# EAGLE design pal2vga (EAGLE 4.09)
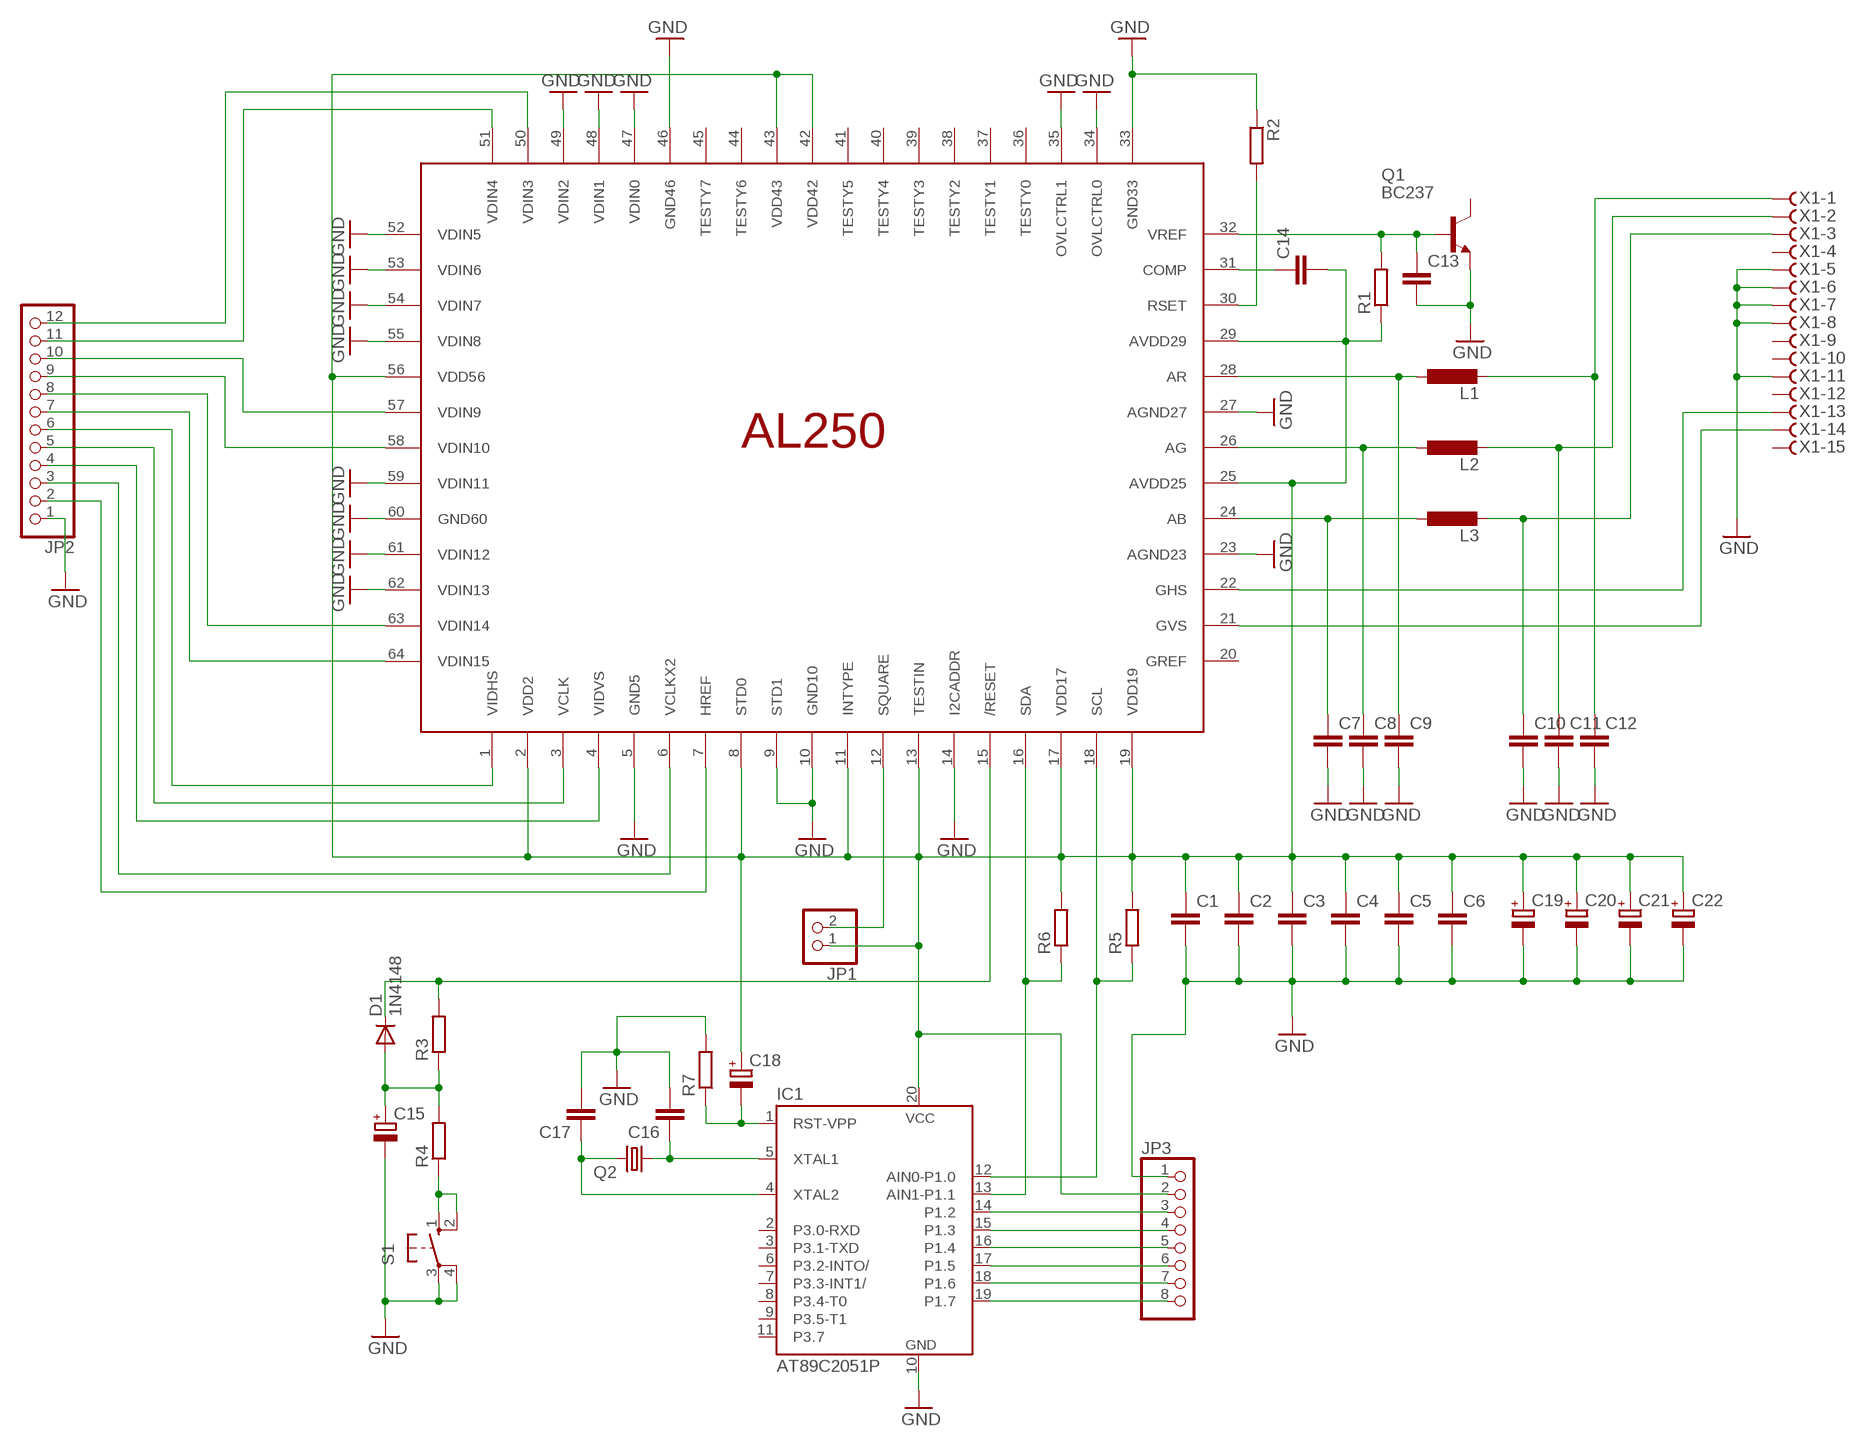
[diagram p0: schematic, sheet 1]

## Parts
C1  C-EUC1206  [C1206]
C2  C-EUC1206  [C1206]
C3  C-EUC1206  [C1206]
C4  C-EUC1206  [C1206]
C5  C-EUC1206  [C1206]
C6  C-EUC1206  [C1206]
C7  C-EUC1206  [C1206]
C8  C-EUC1206  [C1206]
C9  C-EUC1206  [C1206]
C10  C-EUC1206  [C1206]
C11  C-EUC1206  [C1206]
C12  C-EUC1206  [C1206]
C13  C-EUC1206  [C1206]
C14  C-EUC1206  [C1206]
C15  CPOL-EUE2,5-6E  [E2,5-6E]
C16  C-EU050-024X044  [C050-024X044]
C17  C-EU050-024X044  [C050-024X044]
C18  CPOL-EUE3.5-8  [E3,5-8]
C19  CPOL-EUCT6032  [CT6032]
C20  CPOL-EUCT6032  [CT6032]
C21  CPOL-EUCT6032  [CT6032]
C22  CPOL-EUCT6032  [CT6032]
D1  1N4148  [DO35-10]
IC1  AT89C2051P  [DIL20]
JP1  PINHD-1X2  [1X02]
JP2  PINHD-1X12  [1X12]
JP3  PINHD-1X8  [1X08]
L1  L-EUL1812  [L1812]
L2  L-EUL1812  [L1812]
L3  L-EUL1812  [L1812]
Q1  BC237  [TO92]
Q2  CRYTALHC49U-V  [HC49U-V]
R1  R-EU_M1206  [M1206]
R2  R-EU_M1206  [M1206]
R3  R-EU_M1206  [M1206]
R4  R-EU_M1206  [M1206]
R5  R-EU_0207/10  [0207/10]
R6  R-EU_0207/10  [0207/10]
R7  R-EU_0207/10  [0207/10]
S1  10-XX  [B3F-10XX]
U$1  AL250  [QFP64]
X1  F15HDHS  [HDF15H]

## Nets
GND: C1.2 C2.2 C3.2 C4.2 C5.2 C6.2 C7.2 C8.2 C9.2 C10.2 C11.2 C12.2 C13.2 C15.- C16.2 C17.2 C19.- C20.- C21.- C22.- IC1.10(GND) JP2.1 JP3.1 Q1.1(E) R2.1 R7.2 S1.3(P) S1.4(P1) U$1.5(GND5) U$1.9(STD1) U$1.10(GND10) U$1.14(I2CADDR) U$1.23(AGND23) U$1.27(AGND27) U$1.33(GND33) U$1.34(OVLCTRL0) U$1.35(OVLCTRL1) U$1.46(GND46) U$1.47(VDIN0) U$1.48(VDIN1) U$1.49(VDIN2) U$1.52(VDIN5) U$1.53(VDIN6) U$1.54(VDIN7) U$1.55(VDIN8) U$1.59(VDIN11) U$1.60(GND60) U$1.61(VDIN12) U$1.62(VDIN13) X1.5 X1.6 X1.7 X1.8 X1.11
N$1: C13.1 Q1.2(B) R1.2 U$1.32(VREF)
N$2: C14.1 U$1.31(COMP)
N$3: JP1.2 U$1.12(SQUARE)
N$5: JP2.11 U$1.51(VDIN4)
N$7: R2.2 U$1.30(RSET)
N$8: JP2.12 U$1.50(VDIN3)
N$9: U$1.22(GHS) X1.13
N$10: U$1.21(GVS) X1.14
N$11: JP2.10 U$1.57(VDIN9)
N$12: JP2.9 U$1.58(VDIN10)
N$13: JP2.8 U$1.63(VDIN14)
N$14: JP2.7 U$1.64(VDIN15)
N$15: JP2.6 U$1.1(VIDHS)
N$16: IC1.12(AIN0-P1.0) R5.1 U$1.18(SCL)
N$17: IC1.13(AIN1-P1.1) R6.1 U$1.16(SDA)
N$18: JP2.5 U$1.3(VCLK)
N$19: C7.1 L3.1 U$1.24(AB)
N$20: C8.1 L2.1 U$1.26(AG)
N$21: C9.1 L1.1 U$1.28(AR)
N$22: JP2.4 U$1.4(VIDVS)
N$23: JP2.3 U$1.6(VCLKX2)
N$24: JP2.2 U$1.7(HREF)
N$25: C16.1 IC1.5(XTAL1) Q2.1
N$26: C17.1 IC1.4(XTAL2) Q2.2
N$27: C12.1 L1.2 X1.1
N$28: C15.+ D1.A R3.1 R4.2
N$29: C11.1 L2.2 X1.2
N$30: C10.1 L3.2 X1.3
N$32: R4.1 S1.1(S) S1.2(S1)
N$34: C18.- IC1.1(RST-VPP) R7.1
N$35: C1.1 C2.1 C3.1 C4.1 C5.1 C6.1 C14.2 C18.+ C19.+ C20.+ C21.+ C22.+ IC1.20(VCC) JP1.1 JP3.2 R1.1 R5.2 R6.2 U$1.2(VDD2) U$1.8(STD0) U$1.11(INTYPE) U$1.13(TESTIN) U$1.17(VDD17) U$1.19(VDD19) U$1.25(AVDD25) U$1.29(AVDD29) U$1.42(VDD42) U$1.43(VDD43) U$1.56(VDD56)
N$36: D1.C R3.2 U$1.15(/RESET)
N$39: IC1.19(P1.7) JP3.8
N$40: IC1.18(P1.6) JP3.7
N$41: IC1.17(P1.5) JP3.6
N$42: IC1.16(P1.4) JP3.5
N$43: IC1.15(P1.3) JP3.4
N$44: IC1.14(P1.2) JP3.3
Unconnected: IC1.2(P3.0-RXD) IC1.3(P3.1-TXD) IC1.6(P3.2-INTO/) IC1.7(P3.3-INT1/) IC1.8(P3.4-T0) IC1.9(P3.5-T1) IC1.11(P3.7) Q1.3(C) U$1.20(GREF) U$1.36(TESTY0) U$1.37(TESTY1) U$1.38(TESTY2) U$1.39(TESTY3) U$1.40(TESTY4) U$1.41(TESTY5) U$1.44(TESTY6) U$1.45(TESTY7) X1.4 X1.9 X1.10 X1.12 X1.15

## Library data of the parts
C1-C14 C16 C17 = rcl:C-EU: CAPACITOR, European symbol
C15 C18-C22 = rcl:CPOL-EU: POLARIZED CAPACITOR, European symbol
D1 = diode:1N4148: DIODE
IC1 = atmel:AT89C2051: 80C31 MICROCONTROLLER 2 Kbytes FLASH 2.7 V
JP1 = pinhead:PINHD-1X2: PIN HEADER
JP2 = pinhead:PINHD-1X12: PIN HEADER
JP3 = pinhead:PINHD-1X8: PIN HEADER
L1-L3 = rcl:L-EU: INDUCTOR, European symbol
Q1 = transistor-npn:BC237: NPN Transistor
Q2 = crystal:CRYTAL: CRYSTAL
R1-R7 = rcl:R-EU_: RESISTOR, European symbol
S1 = switch-omron:10-XX: OMRON SWITCH
U$1 = averlog:AL250: Averlogic AL250 scandoubler
X1 = con-subd:F15?S: SUB-D

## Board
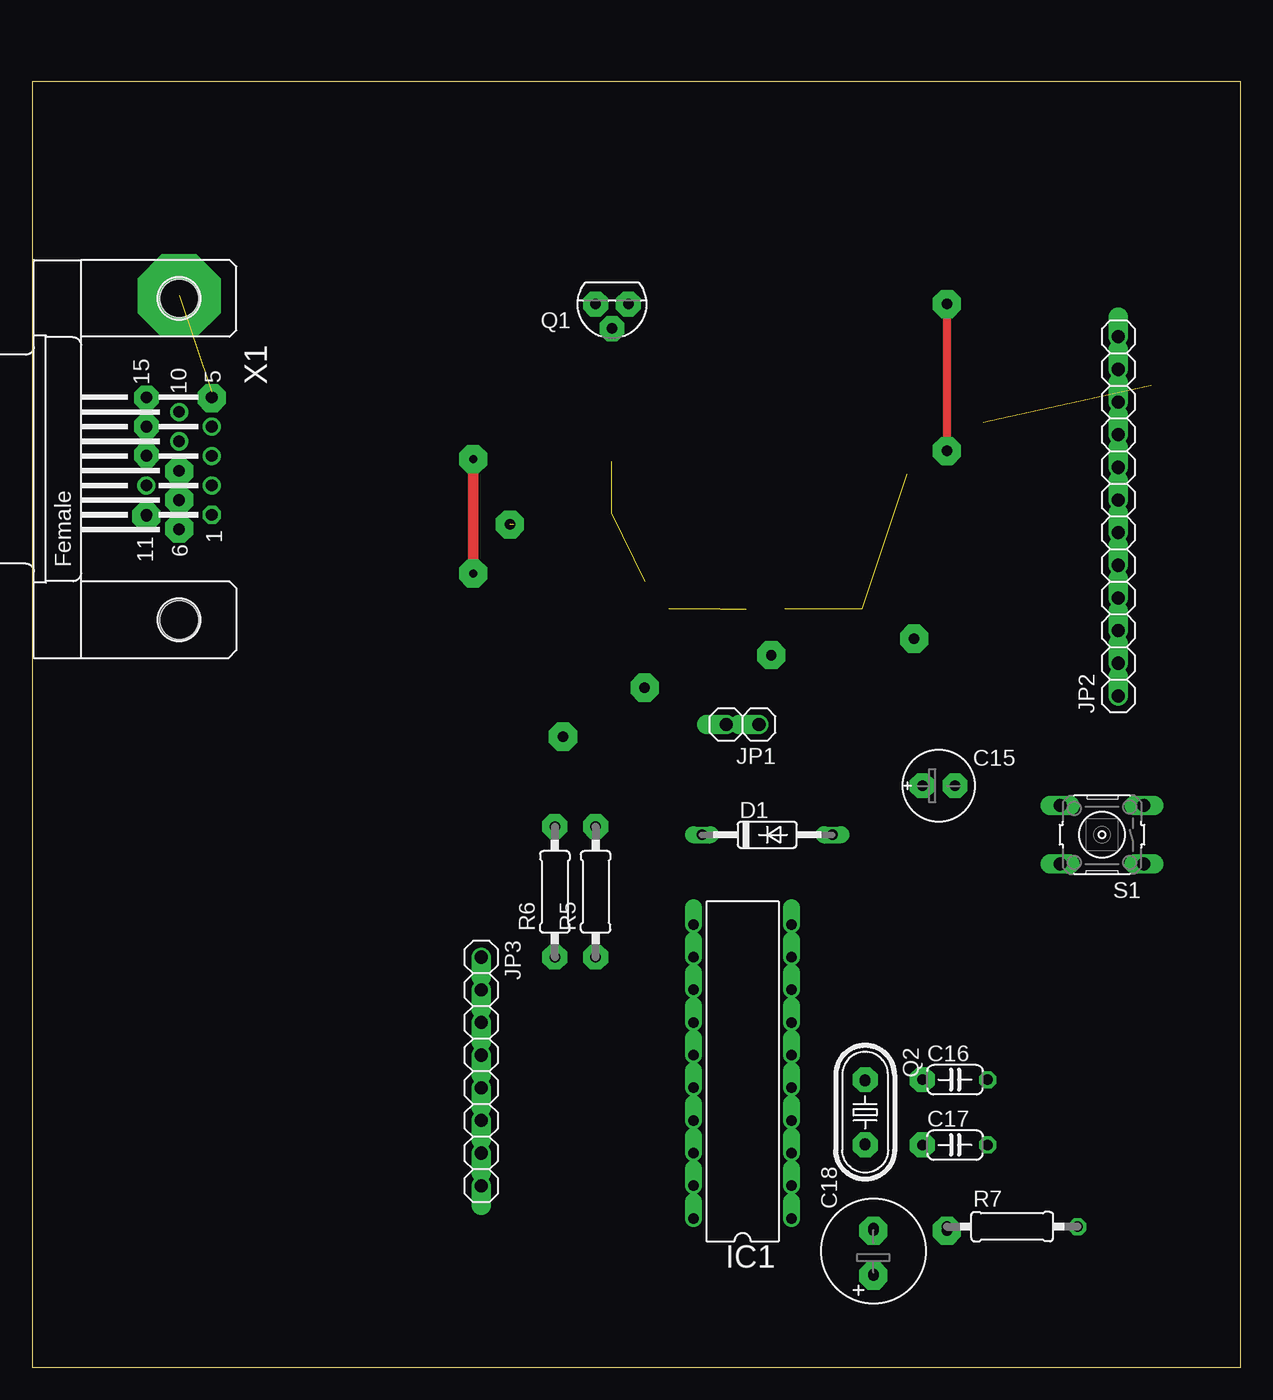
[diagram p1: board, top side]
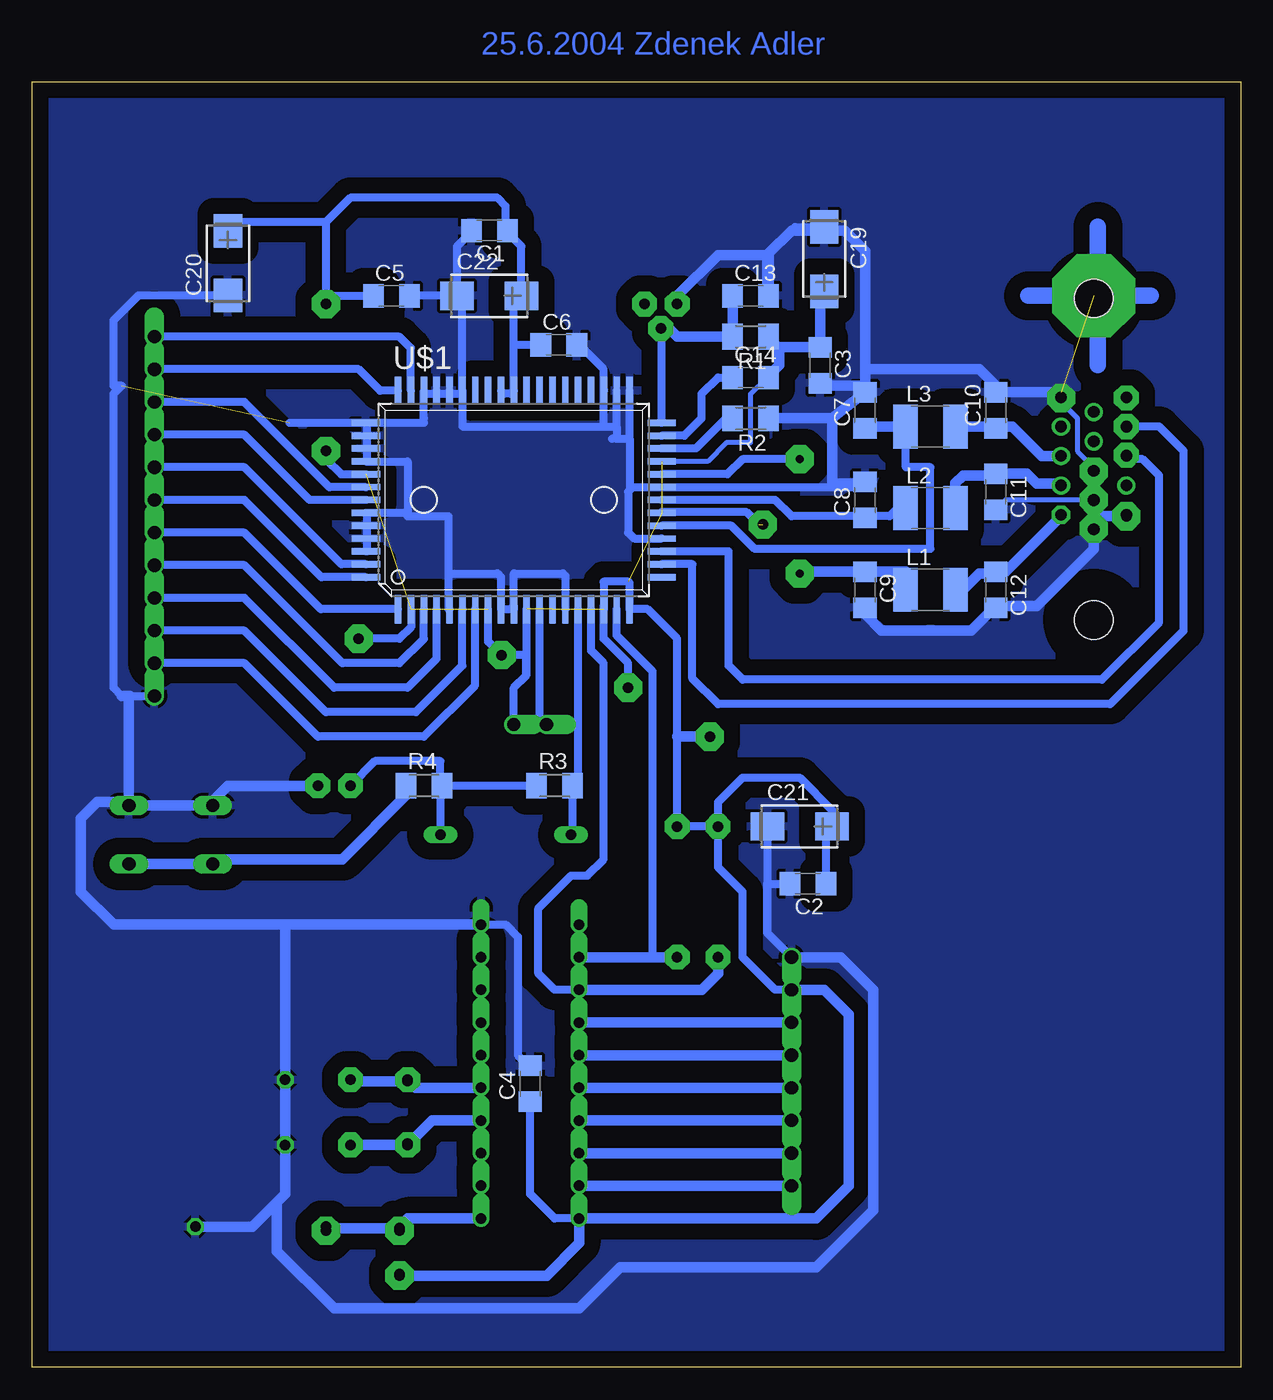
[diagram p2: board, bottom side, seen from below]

Size 93.96 x 100 mm. Coordinates in mm from the lower left corner, seen from the top.
Outline: 0,0 93.96,0 93.96,100 0,100 0,0
Copper layers used: Top, Bottom

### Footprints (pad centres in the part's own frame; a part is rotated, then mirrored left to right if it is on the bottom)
C1206 = smd 1.6 x 1.8: 1 -1.4,0; 2 1.4,0
E2,5-6E = drill 0.813 pad 1.575 round: + -1.27,0 | drill 0.813 pad 1.575 octagon: - 1.27,0
C050-024X044 = drill 0.813 octagon: 1 -2.54,0; 2 2.54,0
E3,5-8 = drill 0.813 pad 1.6 round: + -1.778,0 | drill 0.813 pad 1.6 octagon: - 1.778,0
CT6032 = smd 2.6 x 2.2: + 2.5,0; - -2.5,0
DO35-10 = drill 0.813 long: A 5.08,0; C -5.08,0
DIL20 = drill 0.813 offset: 1 -11.43,-3.81; 2 -8.89,-3.81; 3 -6.35,-3.81; 4 -3.81,-3.81; 5 -1.27,-3.81; 6 1.27,-3.81; 7 3.81,-3.81; 8 6.35,-3.81; 9 8.89,-3.81; 10 11.43,-3.81; 11 11.43,3.81; 12 8.89,3.81; 13 6.35,3.81; 14 3.81,3.81; 15 1.27,3.81; 16 -1.27,3.81; 17 -3.81,3.81; 18 -6.35,3.81; 19 -8.89,3.81; 20 -11.43,3.81
1X02 = drill 1.016 offset: 1 -1.27,0; 2 1.27,0
1X12 = drill 1.016 offset: 1 -13.97,0; 2 -11.43,0; 3 -8.89,0; 4 -6.35,0; 5 -3.81,0; 6 -1.27,0; 7 1.27,0; 8 3.81,0; 9 6.35,0; 10 8.89,0; 11 11.43,0; 12 13.97,0
1X08 = drill 1.016 offset: 1 -8.89,0; 2 -6.35,0; 3 -3.81,0; 4 -1.27,0; 5 1.27,0; 6 3.81,0; 7 6.35,0; 8 8.89,0
L1812 = smd 1.9 x 3.4: 1 -1.95,0; 2 1.95,0
TO92 = drill 0.813 octagon: 1 1.27,0; 2 0,1.905; 3 -1.27,0
HC49U-V = drill 0.813 round: 1 -2.413,0; 2 2.413,0
M1206 = smd 1.6 x 2: 1 -1.4,0; 2 1.4,0
0207/10 = drill 0.813 octagon: 1 -5.08,0; 2 5.08,0
B3F-10XX = drill 1.016 long: 1 -3.251,2.261; 2 3.251,2.261; 3 -3.251,-2.261; 4 3.251,-2.261
QFP64 = smd 0.5 x 2.2: 1 -9,-8.5; 2 -8,-8.5; 3 -7,-8.5; 4 -6,-8.5; 5 -5,-8.5; 6 -4,-8.5; 7 -3,-8.5; 8 -2,-8.5; 9 -1,-8.5; 10 0,-8.5; 11 1,-8.5; 12 2,-8.5; 13 3,-8.5; 14 4,-8.5; 15 5,-8.5; 16 6,-8.5; 17 7,-8.5; 18 8,-8.5; 19 9,-8.5; 33 9,8.5; 34 8,8.5; 35 7,8.5; 36 6,8.5; 37 5,8.5; 38 4,8.5; 39 3,8.5; 40 2,8.5; 41 1,8.5; 42 0,8.5; 43 -1,8.5; 44 -2,8.5; 45 -3,8.5; 46 -4,8.5; 47 -5,8.5; 48 -6,8.5; 49 -7,8.5; 50 -8,8.5; 51 -9,8.5 | smd 2.2 x 0.5: 20 11.5,-6; 21 11.5,-5; 22 11.5,-4; 23 11.5,-3; 24 11.5,-2; 25 11.5,-1; 26 11.5,0; 27 11.5,1; 28 11.5,2; 29 11.5,3; 30 11.5,4; 31 11.5,5; 32 11.5,6; 52 -11.5,6; 53 -11.5,5; 54 -11.5,4; 55 -11.5,3; 56 -11.5,2; 57 -11.5,1; 58 -11.5,0; 59 -11.5,-1; 60 -11.5,-2; 61 -11.5,-3; 62 -11.5,-4; 63 -11.5,-5; 64 -11.5,-6
HDF15H = drill 0.9 octagon: 1 4.329,2.54 | drill 0.9 round: 2 2.043,2.54; 3 -0.243,2.54; 4 -2.529,2.54; 5 -4.815,2.54; 6 5.472,0; 7 3.186,0; 8 0.9,0; 9 -1.386,0; 10 -3.672,0; 11 4.329,-2.54; 12 2.043,-2.54; 13 -0.243,-2.54; 14 -2.529,-2.54; 15 -4.815,-2.54 | hole 3: -12.5,0; 12.5,0

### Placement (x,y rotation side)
C1  58.41,88.42 180 bottom
C2  33.65,37.62 180 bottom
C3  32.7,77.94 270 bottom
C4  55.24,22.06 90 bottom
C5  66.03,83.34 0 bottom
C6  53.02,79.53 0 bottom
C7  29.2,74.45 90 bottom
C8  29.2,67.46 90 bottom
C9  29.2,60.48 270 bottom
C10  19.04,74.45 90 bottom
C11  19.04,68.1 270 bottom
C12  19.04,60.48 270 bottom
C13  38.1,83.34 0 bottom
C14  38.1,76.99 0 bottom
C15  70.48,45.24 0 top
C16  71.75,22.38 0 top
C17  71.75,17.3 0 top
C18  65.4,9.04 90 top
C19  32.38,86.19 270 bottom
C20  78.73,85.88 90 bottom
C21  34.29,42.06 0 bottom
C22  58.41,83.34 0 bottom
D1  57.15,41.43 0 top
IC1  55.24,23.01 90 top
JP1  55.24,50 180 top
JP2  84.45,66.19 90 top
JP3  34.92,23.01 270 top
L1  24.12,60.48 0 bottom
L2  24.12,66.83 0 bottom
L3  24.12,73.18 0 bottom
Q1  45.08,82.7 180 top
Q2  64.77,19.84 270 top
R1  38.1,80.16 180 bottom
R2  38.1,73.81 180 bottom
R3  53.34,45.24 0 bottom
R4  63.5,45.24 0 bottom
R5  43.81,36.98 90 top
R6  40.64,36.98 90 top
R7  76.19,10.95 0 top
S1  83.18,41.43 180 top
U$1  56.51,67.46 0 bottom
X1  11.43,70.64 270 top

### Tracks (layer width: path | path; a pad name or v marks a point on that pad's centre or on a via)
GND  (via drill 0.81 pad 2.18, 0.81 pad 6.45)  (2 unrouted)
  Bottom 0.406: C11.2 18.28,67.46 v11.43,67.46 | X1.5 v13.97,75.4 13.97,75.08 12.7,73.81 12.7,71.27 11.43,70 X1.8
  Bottom 0.61: 29.2,68.73 29.47,68.46 U$1.27 47.26,68.46 47.62,68.1 | U$1.23 47.16,64.46 47.62,64.92 47.62,68.1 | 47.51,72.22 47.51,68.21 47.62,68.1 | 47.51,72.22 U$1.33 | 48.51,73.18 48.51,72.22 | 48.51,72.22 48.89,72.22 | 48.51,72.22 47.51,72.22 | 49.51,73.18 49.53,75.72 | 48.51,73.18 U$1.34 | 49.51,73.18 48.51,73.18 | 49.51,73.18 U$1.35 49.51,76.02 49.53,76.03 49.53,77.62 51.43,79.53 C6.2 | 61.51,75.72 61.59,75.72 | U$1.46 60.51,75.72 61.51,75.72 | U$1.46 60.51,73.18 49.51,73.18 | 61.51,75.72 U$1.47 | 62.51,75.72 61.51,75.72 | 62.51,75.72 U$1.48 | 62.51,75.72 63.51,75.72 U$1.49 63.51,73.81 63.5,73.81 63.5,73.46 U$1.52 | U$1.52 67.94,73.46 67.94,72.46 | 67.94,71.46 67.94,71.27 | 67.94,72.46 U$1.53 | 67.94,72.46 67.94,71.46 | 67.94,71.46 U$1.54 | 67.94,71.46 67.94,70.46 U$1.55 64.77,70.46 64.77,66.46 | 64.77,66.46 U$1.59 67.94,66.46 67.94,65.46 | 67.94,64.46 67.94,64.29 | 67.94,65.46 U$1.60 | 67.94,65.46 67.94,64.46 | U$1.62 67.94,63.46 67.94,64.46 | 67.94,64.46 U$1.61 | 61.59,61.75 61.59,66.19 64.77,66.19 64.77,66.46 | U$1.5 61.59,58.96 61.59,61.75 | 61.59,61.75 57.78,61.75 57.51,61.48 U$1.9 56.76,58.96 56.51,59.21 U$1.10 56.51,61.75 52.7,61.75 52.51,61.56 U$1.14 | 73.94,73.46 U$1.52 | 86.99,52.22 87.62,52.86 87.62,75.72 86.99,76.35 87.62,76.35 87.62,81.43 85.68,83.38 C20.- | 86.35,52.22 JP2.1 | 31.74,73.81 29.2,75.72 29.2,76.35 | 60.96,83.34 C22.- 60.91,87.19 59.69,88.42 C1.2 | U$1.46 60.51,82.89 60.96,83.34 | 36.79,33.77 C21.- | JP3.1 36.79,33.77 | C2.2 36.83,37.62 36.83,33.81 36.79,33.77 | 60.96,83.34 C5.2 | C19.- 34.64,88.69 34.92,88.42 36.83,86.51 | IC1.10 57.15,34.44 56.19,33.49 56.19,24.28 55.24,23.33 C4.2
  Bottom 0.813: X1.5 13.97,75.85 C10.2 19.04,76.35 20.31,77.62 29.2,77.62 | C9.2 29.2,58.57 27.93,57.3 20.95,57.3 19.18,59.08 C12.2 18.91,59.21 15.87,59.21 11.43,63.65 X1.6 v11.43,65.24 11.43,66.19 | 29.2,76.35 C7.2 29.33,75.72 31.74,73.81 | 29.2,76.35 29.2,77.62 | 11.43,66.19 X1.7 v11.43,67.46 | X1.8 v11.43,69.69 v11.43,67.46 | X1.11 9,66.19 11.43,66.19 | v11.43,67.46 11.43,66.19 | 31.74,73.81 31.74,68.73 29.2,68.73 C8.2 | 31.74,73.81 R2.1 | C15.- 78.73,45.24 80,43.97 79.93,43.89 S1.4 S1.3 | S1.3 86.43,52.15 86.35,52.22 86.99,52.22 | S1.3 86.71,43.69 86.99,43.97 | 86.35,43.97 86.43,43.89 S1.3 | Q1.1 43.81,83.34 40.64,86.51 36.83,86.51 36.83,83.34 C13.2 36.7,86.64 34.92,88.42 30.79,88.42 29.2,86.83 29.2,77.62 | 74.29,34.44 87.62,34.44 90.16,36.98 90.16,42.7 88.89,43.97 86.99,43.97 | 74.29,34.44 IC1.10 | 86.99,43.97 86.35,43.97 | 86.35,43.97 86.35,43.33 86.99,43.97 | 74.29,34.44 C16.2 C17.2 74.29,13.49 74.92,12.85 | R7.2 76.83,10.95 74.92,12.85 | JP3.1 31.11,31.9 28.57,29.36 28.57,12.22 33.02,7.77 48.26,7.77 51.43,4.6 70.48,4.6 74.92,9.04 74.92,12.85 | C3.2 32.7,76.35 29.2,76.35
  other vias: 11.43,83.34
  pour Bottom: 47.62,73.18 64.77,73.18 64.77,64.92 61.59,61.75 51.43,61.75 47.62,65.56
  pour Bottom (isolate 1.27): 0.63,99.53 0.63,0.47 93.34,0.47 93.34,99.53
N$1
  Bottom 0.61: U$1.32 45.01,80.73 Q1.2
  Bottom 0.813: Q1.2 44.45,80.8 43.81,80.16 R1.2 39.37,80.16 39.5,80.29 C13.1
N$2
  Bottom 0.61: U$1.31 43.26,72.46 41.91,73.81 41.91,75.72 40.64,76.99 C14.1 39.37,76.99
N$3
  Bottom 0.61: U$1.12 54.51,50.54 JP1.2
N$4  (via drill 0.81 pad 1.93)
  other vias: 8.89,75.4
N$5
  Bottom 0.61: U$1.51 66.91,75.96 68.57,77.62 JP2.11
N$6  (via drill 0.81 pad 2.18)
  Bottom 0.61: 49.53,59.21 49.53,56.67 47.62,54.76 v47.62,52.86
N$7
  Bottom 0.61: U$1.30 42.35,71.46 40,73.81 R2.2 39.37,73.81
N$8
  Bottom 0.61: U$1.50 64.51,79.27 65.4,80.16 JP2.12
N$9
  Bottom 0.61: U$1.22 39.81,63.46 39.81,54.57 38.73,53.49 10.79,53.49 6.34,57.94 6.34,69.37 7.62,70.64 8.89,70.64 X1.13
N$10  (via drill 0.81 pad 1.93)
  Bottom 0.61: U$1.21 42.62,62.46 42.62,53.57 40.64,51.59 10.16,51.59 4.44,57.3 4.44,71.27 6.34,73.18 v8.89,73.18 X1.14
N$11
  Bottom 0.61: U$1.57 70.84,68.46 77.46,75.08 JP2.10
N$12
  Bottom 0.61: U$1.58 72.38,67.46 77.46,72.54 JP2.9
N$13
  Bottom 0.61: U$1.63 69.92,62.46 77.46,70 JP2.8
N$14
  Bottom 0.61: U$1.64 71.46,61.46 77.46,67.46 JP2.7
N$15
  Bottom 0.61: U$1.1 71.5,58.96 77.46,64.92 JP2.6
N$16
  Bottom 0.61: U$1.18 48.51,56.92 45.72,54.13 45.72,31.9
  Bottom 0.813: R5.1 45.72,31.9 IC1.12
N$17
  Bottom 0.61: U$1.16 50.51,55.75 49.53,54.76 49.53,39.52 50.8,38.25 52.07,38.25 54.61,35.71 54.61,30.63 53.34,29.36 IC1.13
  Bottom 0.813: R6.1 40.64,30.63 41.91,29.36 IC1.13
N$18
  Bottom 0.61: U$1.3 63.51,56.65 65.4,54.76 69.84,54.76 77.46,62.38 JP2.5
N$19
  Bottom 0.61: U$1.24 39.59,65.46 37.78,63.65 24.12,63.65 24.12,70 26.03,70 26.03,73.18 L3.1
  Bottom 0.813: C7.1 29.2,73.18 L3.1
N$20
  Bottom 0.61: L2.1 26.66,66.83 27.3,66.19 29.2,66.19 | U$1.26 36.19,67.46 34.92,66.19 29.2,66.19 | 29.2,66.19 C8.1
N$21  (via drill 0.61 pad 2.18)
  Top 0.813: v34.29,61.75 v34.29,70.64
  Bottom 0.61: v34.29,70.64 38.73,70.64 39.91,69.46 U$1.28
  Bottom 0.813: L1.1 26.03,60.48 26.03,61.88 C9.1 33.15,61.88 v34.29,61.75
N$22
  Bottom 0.61: U$1.4 62.51,55.11 64.77,52.86 70.48,52.86 77.46,59.84 JP2.4
N$23
  Bottom 0.61: U$1.6 60.51,54.57 64.13,50.95 71.11,50.95 77.46,57.3 JP2.3
N$24
  Bottom 0.61: U$1.7 59.51,53.03 63.5,49.05 71.75,49.05 77.46,54.76 JP2.2
N$25  (via drill 0.81 pad 1.93)
  Bottom 0.813: IC1.5 64.13,21.74 v64.77,22.38 Q2.1 69.08,22.25 C16.1
N$26  (via drill 0.81 pad 1.93)
  Bottom 0.813: IC1.4 62.86,19.2 v64.77,17.3 | v64.77,17.3 Q2.2 | v64.77,17.3 C17.1
N$27
  Bottom 0.813: X1.1 13.97,66.19 18.28,61.88 C12.1 19.04,61.75 20.31,61.75 21.58,60.48 L1.2
N$28
  Bottom 0.61: R3.1 R4.2 62.23,45.24 | 62.23,45.24 D1.A | C15.+ 67.3,47.14 62.23,47.14 62.23,45.24
N$29
  Bottom 0.813: X1.2 13.97,68.73 15.87,68.73 16.63,69.5 C11.1 19.04,69.37 21.58,69.37 22.18,68.78 L2.2
N$30
  Bottom 0.813: 19.04,73.18 L3.2 | X1.3 15.48,70.88 17.77,73.18 19.04,73.18 | 19.04,73.18 C10.1
N$31  (via drill 0.81 pad 2.18)
  other vias: 8.89,66.19
N$32
  Bottom 0.813: R4.1 64.89,44.47 69.84,39.52 79.37,39.52 79.93,38.96 | 79.93,38.96 80,38.89 | 79.93,38.96 S1.2 86.08,39.17 86.35,38.89 86.43,38.96 S1.1
N$33  (via drill 0.81 pad 2.18)
  Bottom 0.61: 64.45,58.89 64.45,57.62 65.4,56.67 v68.57,56.67
N$34
  Bottom 0.813: IC1.1 64.77,11.58 65.4,10.95 C18.- 70.99,10.82 R7.1
N$35  (via drill 0.81 pad 2.18)  (6 unrouted)
  Top 0.61: v71.11,82.7 v71.11,71.27
  Bottom 0.406: C14.2 36.83,76.99 38.1,75.72 38.1,71.91 40,71.91 41.45,70.46 U$1.29
  Bottom 0.61: U$1.43 57.27,75.72 56.76,75.72 U$1.42 56.51,79.53 | U$1.17 49.51,61.1 49.53,61.11 47.62,61.11 47.51,61 U$1.19 46.11,58.96 43.81,56.67 43.81,49.05 R5.2 | U$1.11 55.51,53.86 55.56,53.81 | 55.56,53.81 56.51,52.86 JP1.1 | R6.2 R5.2 | R6.2 R5.2 | 56.51,79.53 56.51,82.7 55.88,83.34 C22.+ 55.91,87.19 57.15,88.42 | 57.15,88.42 C1.1 | R6.2 40.64,43.97 38.73,45.87 34.29,45.87 31.74,43.33 31.74,42.06 | JP3.2 36.19,29.36 38.73,31.9 38.73,36.98 40.64,38.89 R6.2 | C2.1 32.25,41.93 32.38,42.06 31.74,42.06 | 31.74,42.06 C21.+ | U$1.56 69.94,69.46 71.11,70.64 v71.11,71.27 | 71.11,89.05 v71.11,82.7 70.48,83.34 C5.1 | 71.11,89.05 69.21,90.96 57.78,90.96 57.15,90.32 57.15,88.42 | C20.+ 78.73,88.42 78.1,89.05 71.11,89.05 | 56.51,79.53 C6.1 | IC1.20 53.34,11.58 55.24,13.49 C4.1 55.24,20.79 | U$1.8 58.51,56.45 57.46,55.4 55.56,55.4 55.56,53.81
  Bottom 0.813: C18.+ 65.4,7.14 53.97,7.14 51.43,9.68 IC1.20 33.02,11.58 30.47,14.12 30.47,27.46 32.38,29.36 JP3.2 | R1.1 36.83,80.16 36,79.34 | 36,79.34 C3.1 32.7,83.02 32.38,83.34 C19.+ | C14.2 36.7,77.12 35.87,77.94 35.87,79.21 36,79.34 | 43.81,49.05 v41.27,49.05
N$36
  Bottom 0.61: U$1.15 51.51,45.79 52.07,45.24 R3.2 51.94,41.56 D1.C
N$37  (via drill 0.81 pad 2.18)  (1 unrouted)
  Bottom 0.61: 45.08,66.51 38.41,66.51 37.46,65.56
  other vias: 37.14,65.56
N$38  (via drill 0.81 pad 2.18)
  other vias: 57.46,55.4
N$39
  Bottom 0.813: JP3.8 IC1.19
N$40
  Bottom 0.813: JP3.7 IC1.18
N$41
  Bottom 0.813: JP3.6 IC1.17
N$42
  Bottom 0.813: JP3.5 IC1.16
N$43
  Bottom 0.813: JP3.4 IC1.15
N$44
  Bottom 0.813: JP3.3 IC1.14
N$45  (via drill 0.81 pad 1.93)
  other vias: 8.89,70.95
N$46  (via drill 0.81 pad 1.93)
  other vias: 69.21,22.38
N$47  (via drill 0.81 pad 1.93)
  other vias: 69.21,17.3
N$48  (via drill 0.81 pad 1.93)
  other vias: 40.64,31.9
N$49  (via drill 0.81 pad 1.93)
  other vias: 43.81,31.9
N$50  (via drill 0.81 pad 1.93)
  other vias: 43.81,42.06
N$51  (via drill 0.81 pad 1.93)
  other vias: 40.64,42.06
N$52  (via drill 0.81 pad 1.93)
  other vias: 69.21,45.24
N$53  (via drill 0.81 pad 1.93)
  other vias: 71.75,45.24
N$54
  Bottom 1.27: 11.11,88.73 11.11,77.94
N$55
  Bottom 1.27: 16.5,83.34 6.98,83.34
N$56  (via drill 0.81 pad 1.93)
  other vias: 43.81,82.7
N$57  (via drill 0.81 pad 1.93)
  other vias: 45.08,80.8
N$58  (via drill 0.81 pad 1.93)
  other vias: 46.35,82.7
N$59  (via drill 0.81 pad 2.18)
  other vias: 71.11,10.63
N$60  (via drill 0.81 pad 2.18)
  other vias: 65.4,7.14
N$61  (via drill 0.81 pad 2.18)
  other vias: 65.4,10.63

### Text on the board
Bottom: 25.6.2004 Zdenek Adler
